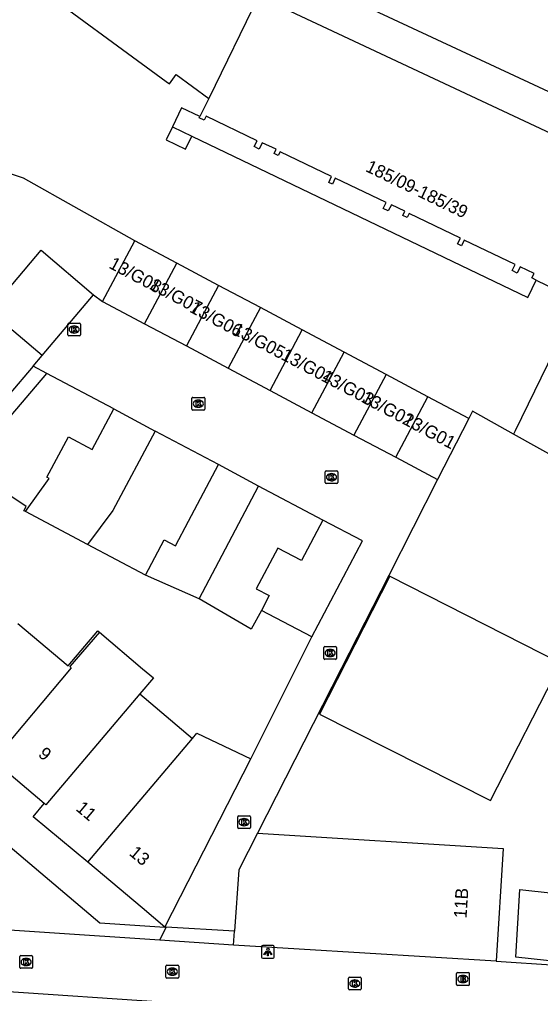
# Model space of a CAD drawing. Extents: x 160356 to 161355, y 381727 to 382845.
# Drawn here: x 160581.4 to 160622.2, y 382224.6 to 382300.8 of the extents above; entities that cross this region are included whole.
import ezdxf

# ---------------------------------------------------------------- set-up
doc = ezdxf.new("R2010")
doc.units = 0
for name, color, linetype in [('IMGEO_Brandkraan', 7, 'Continuous'), ('IMGEO_Kolk', 7, 'Continuous'), ('IMGEO_Lichtpunt', 7, 'Continuous'), ('IMGEO_Muur', 7, 'Continuous'), ('IMGEO_Pand', 7, 'Continuous'), ('IMGEO_Pand_nummerreeks', 7, 'Continuous'), ('IMGEO_Rijbaan_lokaal_open', 7, 'Continuous'), ('IMGEO_Voetpad_op_trap', 7, 'Continuous'), ('IMGEO_Voetpad_open', 7, 'Continuous')]:
    doc.layers.add(name, color=color, linetype=linetype)

msp = doc.modelspace()

# ---------------------------------------------------------------- linework, layer by layer
at = {"layer": 'IMGEO_Brandkraan'}
for p, q in [((160615.608, 382225.283), (160615.608, 382226.135)), ((160615.683, 382226.209), (160616.535, 382226.209)), ((160616.096, 382225.989), (160616.121, 382225.989)), ((160616.609, 382226.135), (160616.609, 382225.283)), ((160616.535, 382225.209), (160615.683, 382225.209)), ((160616.119, 382225.429), (160616.094, 382225.429))]:
    msp.add_line(p, q, dxfattribs=at)
for points in [[(160615.608, 382225.283), (160615.608, 382226.135)], [(160615.683, 382226.209), (160616.535, 382226.209)], [(160616.609, 382226.135), (160616.609, 382225.283)], [(160616.535, 382225.209), (160615.683, 382225.209)], [(160615.956, 382225.909), (160615.956, 382225.509), (160616.169, 382225.509)], [(160616.187, 382225.909), (160615.956, 382225.909)], [(160616.135, 382225.828), (160616.081, 382225.828), (160616.081, 382225.752)], [(160616.081, 382225.752), (160616.134, 382225.752)], [(160616.143, 382225.676), (160616.081, 382225.676), (160616.081, 382225.595)], [(160616.081, 382225.595), (160616.143, 382225.595)]]:
    msp.add_lwpolyline(points, dxfattribs=at)
for centre, radius, start, end in [((160615.685, 382226.133), 0.0765, 91.55205, 178.44795), ((160615.685, 382226.133), 0.0765, 91.55205, 178.44795), ((160616.533, 382226.133), 0.0765, 1.55205, 88.44795), ((160616.533, 382226.133), 0.0765, 1.55205, 88.44795), ((160615.685, 382225.285), 0.0765, 181.55205, 268.44795), ((160615.685, 382225.285), 0.0765, 181.55205, 268.44795), ((160616.136, 382225.79), 0.0379, 267.82845, 90.93552), ((160616.144, 382225.635), 0.0404, 269.87594, 90.50774), ((160616.175, 382225.76), 0.251, 268.66757, 293.53466), ((160616.191, 382225.764), 0.145, 59.4692, 91.53667), ((160616.216, 382225.811), 0.0922, 285.51372, 58.15012), ((160616.221, 382225.619), 0.105, 301.31148, 78.98903), ((160616.533, 382225.285), 0.0765, 271.55205, 358.44795), ((160616.533, 382225.285), 0.0765, 271.55205, 358.44795)]:
    msp.add_arc(centre, radius, start, end, dxfattribs=at)
for centre, major_axis, ratio, start_param, end_param in [((160616.095, 382225.709), (-0.387, 0.002), 0.722429, 4.712389, 7.853982), ((160616.12, 382225.709), (-0.39, 0.002), 0.717154, 1.570796, 4.712389)]:
    msp.add_ellipse(centre, major_axis=major_axis, ratio=ratio, start_param=start_param, end_param=end_param, dxfattribs=at)
at = {"layer": 'IMGEO_Kolk'}
for p, q in [((160585.247, 382277.054), (160586.099, 382277.054)), ((160585.172, 382276.128), (160585.172, 382276.98)), ((160585.683, 382276.274), (160585.658, 382276.274)), ((160585.66, 382276.834), (160585.685, 382276.834)), ((160586.173, 382276.98), (160586.173, 382276.128)), ((160586.099, 382276.054), (160585.247, 382276.054)), ((160594.892, 382270.312), (160594.892, 382271.164)), ((160594.967, 382271.238), (160595.819, 382271.238)), ((160595.38, 382271.018), (160595.405, 382271.018)), ((160595.893, 382271.164), (160595.893, 382270.312)), ((160595.819, 382270.238), (160594.967, 382270.238)), ((160595.403, 382270.458), (160595.378, 382270.458)), ((160605.318, 382264.562), (160605.318, 382265.414)), ((160605.393, 382265.488), (160606.245, 382265.488)), ((160605.806, 382265.268), (160605.831, 382265.268)), ((160606.319, 382265.414), (160606.319, 382264.562)), ((160606.245, 382264.488), (160605.393, 382264.488)), ((160605.829, 382264.708), (160605.804, 382264.708)), ((160605.211, 382250.806), (160605.211, 382251.658)), ((160605.286, 382251.732), (160606.138, 382251.732)), ((160605.699, 382251.512), (160605.724, 382251.512)), ((160606.212, 382251.658), (160606.212, 382250.806)), ((160606.138, 382250.732), (160605.286, 382250.732)), ((160605.722, 382250.952), (160605.697, 382250.952)), ((160598.475, 382237.562), (160598.475, 382238.414)), ((160598.55, 382238.488), (160599.402, 382238.488)), ((160598.963, 382238.268), (160598.988, 382238.268)), ((160599.476, 382238.414), (160599.476, 382237.562)), ((160599.402, 382237.488), (160598.55, 382237.488)), ((160598.986, 382237.708), (160598.961, 382237.708)), ((160581.411, 382226.62), (160581.411, 382227.472)), ((160581.486, 382227.546), (160582.338, 382227.546)), ((160582.412, 382227.472), (160582.412, 382226.62)), ((160581.922, 382226.766), (160581.897, 382226.766)), ((160581.899, 382227.326), (160581.924, 382227.326)), ((160592.857, 382225.86), (160592.857, 382226.712)), ((160592.932, 382226.786), (160593.784, 382226.786)), ((160593.858, 382226.712), (160593.858, 382225.86)), ((160582.338, 382226.546), (160581.486, 382226.546)), ((160593.368, 382226.006), (160593.343, 382226.006)), ((160593.345, 382226.566), (160593.37, 382226.566)), ((160593.784, 382225.786), (160592.932, 382225.786)), ((160607.141, 382224.926), (160607.141, 382225.778)), ((160607.216, 382225.852), (160608.068, 382225.852)), ((160607.629, 382225.632), (160607.654, 382225.632)), ((160608.142, 382225.778), (160608.142, 382224.926)), ((160608.068, 382224.852), (160607.216, 382224.852)), ((160607.652, 382225.072), (160607.627, 382225.072))]:
    msp.add_line(p, q, dxfattribs=at)
for points in [[(160585.247, 382277.054), (160586.099, 382277.054)], [(160585.172, 382276.128), (160585.172, 382276.98)], [(160585.493, 382276.754), (160585.616, 382276.754), (160585.616, 382276.603), (160585.746, 382276.754), (160585.91, 382276.754), (160585.764, 382276.603), (160585.917, 382276.354), (160585.765, 382276.354), (160585.68, 382276.518), (160585.616, 382276.451), (160585.616, 382276.354), (160585.493, 382276.354), (160585.493, 382276.754)], [(160586.173, 382276.98), (160586.173, 382276.128)], [(160586.099, 382276.054), (160585.247, 382276.054)], [(160594.892, 382270.312), (160594.892, 382271.164)], [(160594.967, 382271.238), (160595.819, 382271.238)], [(160595.213, 382270.938), (160595.336, 382270.938), (160595.336, 382270.787), (160595.466, 382270.938), (160595.63, 382270.938), (160595.484, 382270.787), (160595.637, 382270.538), (160595.485, 382270.538), (160595.4, 382270.702), (160595.336, 382270.635), (160595.336, 382270.538), (160595.213, 382270.538), (160595.213, 382270.938)], [(160595.893, 382271.164), (160595.893, 382270.312)], [(160595.819, 382270.238), (160594.967, 382270.238)], [(160605.318, 382264.562), (160605.318, 382265.414)], [(160605.393, 382265.488), (160606.245, 382265.488)], [(160605.639, 382265.188), (160605.762, 382265.188), (160605.762, 382265.037), (160605.892, 382265.188), (160606.056, 382265.188), (160605.91, 382265.037), (160606.063, 382264.788), (160605.911, 382264.788), (160605.826, 382264.952), (160605.762, 382264.885), (160605.762, 382264.788), (160605.639, 382264.788), (160605.639, 382265.188)], [(160606.319, 382265.414), (160606.319, 382264.562)], [(160606.245, 382264.488), (160605.393, 382264.488)], [(160605.211, 382250.806), (160605.211, 382251.658)], [(160605.286, 382251.732), (160606.138, 382251.732)], [(160605.532, 382251.432), (160605.655, 382251.432), (160605.655, 382251.281), (160605.785, 382251.432), (160605.949, 382251.432), (160605.803, 382251.281), (160605.956, 382251.032), (160605.804, 382251.032), (160605.719, 382251.196), (160605.655, 382251.129), (160605.655, 382251.032), (160605.532, 382251.032), (160605.532, 382251.432)], [(160606.212, 382251.658), (160606.212, 382250.806)], [(160606.138, 382250.732), (160605.286, 382250.732)], [(160598.475, 382237.562), (160598.475, 382238.414)], [(160598.55, 382238.488), (160599.402, 382238.488)], [(160598.796, 382238.188), (160598.919, 382238.188), (160598.919, 382238.037), (160599.049, 382238.188), (160599.213, 382238.188), (160599.067, 382238.037), (160599.22, 382237.788), (160599.068, 382237.788), (160598.983, 382237.952), (160598.919, 382237.885), (160598.919, 382237.788), (160598.796, 382237.788), (160598.796, 382238.188)], [(160599.476, 382238.414), (160599.476, 382237.562)], [(160599.402, 382237.488), (160598.55, 382237.488)], [(160581.411, 382226.62), (160581.411, 382227.472)], [(160581.486, 382227.546), (160582.338, 382227.546)], [(160582.412, 382227.472), (160582.412, 382226.62)], [(160581.732, 382227.246), (160581.855, 382227.246), (160581.855, 382227.095), (160581.985, 382227.246), (160582.149, 382227.246), (160582.003, 382227.095), (160582.156, 382226.846), (160582.004, 382226.846), (160581.919, 382227.01), (160581.855, 382226.943), (160581.855, 382226.846), (160581.732, 382226.846), (160581.732, 382227.246)], [(160592.857, 382225.86), (160592.857, 382226.712)], [(160592.932, 382226.786), (160593.784, 382226.786)], [(160593.858, 382226.712), (160593.858, 382225.86)], [(160582.338, 382226.546), (160581.486, 382226.546)], [(160593.178, 382226.486), (160593.301, 382226.486), (160593.301, 382226.335), (160593.431, 382226.486), (160593.595, 382226.486), (160593.449, 382226.335), (160593.602, 382226.086), (160593.45, 382226.086), (160593.365, 382226.25), (160593.301, 382226.183), (160593.301, 382226.086), (160593.178, 382226.086), (160593.178, 382226.486)], [(160593.784, 382225.786), (160592.932, 382225.786)], [(160607.141, 382224.926), (160607.141, 382225.778)], [(160607.216, 382225.852), (160608.068, 382225.852)], [(160607.462, 382225.552), (160607.585, 382225.552), (160607.585, 382225.401), (160607.715, 382225.552), (160607.879, 382225.552), (160607.733, 382225.401), (160607.886, 382225.152), (160607.734, 382225.152), (160607.649, 382225.316), (160607.585, 382225.249), (160607.585, 382225.152), (160607.462, 382225.152), (160607.462, 382225.552)], [(160608.142, 382225.778), (160608.142, 382224.926)], [(160608.068, 382224.852), (160607.216, 382224.852)]]:
    msp.add_lwpolyline(points, dxfattribs=at)
for centre, start, end in [((160585.249, 382276.978), 91.55205, 178.44795), ((160585.249, 382276.978), 91.55205, 178.44795), ((160586.097, 382276.978), 1.55205, 88.44795), ((160586.097, 382276.978), 1.55205, 88.44795), ((160585.249, 382276.13), 181.55205, 268.44795), ((160585.249, 382276.13), 181.55205, 268.44795), ((160586.097, 382276.13), 271.55205, 358.44795), ((160586.097, 382276.13), 271.55205, 358.44795), ((160594.969, 382271.162), 91.55205, 178.44795), ((160594.969, 382271.162), 91.55205, 178.44795), ((160595.817, 382271.162), 1.55205, 88.44795), ((160595.817, 382271.162), 1.55205, 88.44795), ((160594.969, 382270.314), 181.55205, 268.44795), ((160594.969, 382270.314), 181.55205, 268.44795), ((160595.817, 382270.314), 271.55205, 358.44795), ((160595.817, 382270.314), 271.55205, 358.44795), ((160605.395, 382265.412), 91.55205, 178.44795), ((160605.395, 382265.412), 91.55205, 178.44795), ((160606.243, 382265.412), 1.55205, 88.44795), ((160606.243, 382265.412), 1.55205, 88.44795), ((160605.395, 382264.564), 181.55205, 268.44795), ((160605.395, 382264.564), 181.55205, 268.44795), ((160606.243, 382264.564), 271.55205, 358.44795), ((160606.243, 382264.564), 271.55205, 358.44795), ((160605.288, 382251.656), 91.55205, 178.44795), ((160605.288, 382251.656), 91.55205, 178.44795), ((160606.136, 382251.656), 1.55205, 88.44795), ((160606.136, 382251.656), 1.55205, 88.44795), ((160605.288, 382250.808), 181.55205, 268.44795), ((160605.288, 382250.808), 181.55205, 268.44795), ((160606.136, 382250.808), 271.55205, 358.44795), ((160606.136, 382250.808), 271.55205, 358.44795), ((160598.552, 382238.412), 91.55205, 178.44795), ((160598.552, 382238.412), 91.55205, 178.44795), ((160599.4, 382238.412), 1.55205, 88.44795), ((160599.4, 382238.412), 1.55205, 88.44795), ((160598.552, 382237.564), 181.55205, 268.44795), ((160598.552, 382237.564), 181.55205, 268.44795), ((160599.4, 382237.564), 271.55205, 358.44795), ((160599.4, 382237.564), 271.55205, 358.44795), ((160581.488, 382227.47), 91.55205, 178.44795), ((160581.488, 382227.47), 91.55205, 178.44795), ((160582.336, 382227.47), 1.55205, 88.44795), ((160582.336, 382227.47), 1.55205, 88.44795), ((160592.934, 382226.71), 91.55205, 178.44795), ((160592.934, 382226.71), 91.55205, 178.44795), ((160593.782, 382226.71), 1.55205, 88.44795), ((160593.782, 382226.71), 1.55205, 88.44795), ((160581.488, 382226.622), 181.55205, 268.44795), ((160581.488, 382226.622), 181.55205, 268.44795), ((160582.336, 382226.622), 271.55205, 358.44795), ((160582.336, 382226.622), 271.55205, 358.44795), ((160592.934, 382225.862), 181.55205, 268.44795), ((160592.934, 382225.862), 181.55205, 268.44795), ((160593.782, 382225.862), 271.55205, 358.44795), ((160593.782, 382225.862), 271.55205, 358.44795), ((160607.218, 382225.776), 91.55205, 178.44795), ((160607.218, 382225.776), 91.55205, 178.44795), ((160608.066, 382225.776), 1.55205, 88.44795), ((160608.066, 382225.776), 1.55205, 88.44795), ((160607.218, 382224.928), 181.55205, 268.44795), ((160607.218, 382224.928), 181.55205, 268.44795), ((160608.066, 382224.928), 271.55205, 358.44795), ((160608.066, 382224.928), 271.55205, 358.44795)]:
    msp.add_arc(centre, 0.0765, start, end, dxfattribs=at)
for centre, major_axis, ratio, start_param, end_param in [((160585.659, 382276.554), (-0.387, 0.002), 0.722429, 4.712389, 7.853982), ((160585.684, 382276.554), (-0.39, 0.002), 0.717154, 1.570796, 4.712389), ((160595.379, 382270.738), (-0.387, 0.002), 0.722429, 4.712389, 7.853982), ((160595.404, 382270.738), (-0.39, 0.002), 0.717154, 1.570796, 4.712389), ((160605.805, 382264.988), (-0.387, 0.002), 0.722429, 4.712389, 7.853982), ((160605.83, 382264.988), (-0.39, 0.002), 0.717154, 1.570796, 4.712389), ((160605.698, 382251.232), (-0.387, 0.002), 0.722429, 4.712389, 7.853982), ((160605.723, 382251.232), (-0.39, 0.002), 0.717154, 1.570796, 4.712389), ((160598.962, 382237.988), (-0.387, 0.002), 0.722429, 4.712389, 7.853982), ((160598.987, 382237.988), (-0.39, 0.002), 0.717154, 1.570796, 4.712389), ((160581.898, 382227.046), (-0.387, 0.002), 0.722429, 4.712389, 7.853982), ((160581.923, 382227.046), (-0.39, 0.002), 0.717154, 1.570796, 4.712389), ((160593.344, 382226.286), (-0.387, 0.002), 0.722429, 4.712389, 7.853982), ((160593.369, 382226.286), (-0.39, 0.002), 0.717154, 1.570796, 4.712389), ((160607.628, 382225.352), (-0.387, 0.002), 0.722429, 4.712389, 7.853982), ((160607.653, 382225.352), (-0.39, 0.002), 0.717154, 1.570796, 4.712389)]:
    msp.add_ellipse(centre, major_axis=major_axis, ratio=ratio, start_param=start_param, end_param=end_param, dxfattribs=at)
at = {"layer": 'IMGEO_Lichtpunt'}
for p, q in [((160600.345, 382228.233), (160600.345, 382227.426)), ((160600.345, 382228.233), (160600.345, 382227.426)), ((160601.247, 382228.328), (160600.439, 382228.328)), ((160601.247, 382228.328), (160600.439, 382228.328)), ((160601.341, 382227.426), (160601.341, 382228.233)), ((160601.341, 382227.426), (160601.341, 382228.233)), ((160600.439, 382227.332), (160601.247, 382227.332)), ((160600.439, 382227.332), (160601.247, 382227.332))]:
    msp.add_line(p, q, dxfattribs=at)
for points in [[(160600.719, 382227.897), (160600.758, 382227.869), (160600.57, 382227.607), (160600.532, 382227.634), (160600.719, 382227.897)], [(160600.821, 382227.849), (160600.868, 382227.849), (160600.868, 382227.527), (160600.821, 382227.527), (160600.821, 382227.849)], [(160600.931, 382227.869), (160600.969, 382227.896), (160601.156, 382227.634), (160601.117, 382227.606), (160600.931, 382227.869)]]:
    msp.add_lwpolyline(points, dxfattribs=at)
msp.add_circle((160600.844, 382228.031), 0.0994, dxfattribs=at)
for centre, start, end in [((160600.439, 382228.233), 90, 180), ((160600.439, 382228.233), 90, 180), ((160601.247, 382228.233), 0, 90), ((160601.247, 382228.233), 0, 90), ((160600.439, 382227.426), 180, 270), ((160600.439, 382227.426), 180, 270), ((160601.247, 382227.426), 270, 0), ((160601.247, 382227.426), 270, 360)]:
    msp.add_arc(centre, 0.0946, start, end, dxfattribs=at)
at = {"layer": 'IMGEO_Muur'}
msp.add_lwpolyline([(160618.701, 382227.096), (160628.15, 382226.469), (160633.664, 382237.246)], dxfattribs=at)
at = {"layer": 'IMGEO_Pand'}
for points in [[(160602.684, 382304.568), (160625.056, 382294.138)], [(160581.837, 382304.092), (160592.884, 382295.963), (160593.126, 382295.785), (160593.659, 382296.51), (160596.203, 382294.64)], [(160600.114, 382302.653), (160596.203, 382294.64)], [(160628.955, 382264.141), (160632.865, 382272.306), (160632.67, 382272.4), (160637.325, 382282.078), (160635.529, 382282.942), (160636.742, 382285.453), (160600.114, 382302.653)], [(160596.203, 382294.64), (160595.507, 382293.214)], [(160621.852, 382280.417), (160621.509, 382280.583), (160621.68, 382280.944), (160620.592, 382281.465), (160620.354, 382280.969), (160619.962, 382281.157), (160620.195, 382281.644), (160616.209, 382283.552), (160615.993, 382283.101), (160615.696, 382283.244), (160615.912, 382283.695), (160611.891, 382285.62), (160611.746, 382285.318), (160611.408, 382285.48), (160611.563, 382285.804), (160610.504, 382286.312), (160610.261, 382285.829), (160609.874, 382286.024), (160610.108, 382286.489), (160606.113, 382288.392), (160605.885, 382287.926), (160605.598, 382288.068), (160605.828, 382288.524), (160601.801, 382290.464), (160601.654, 382290.168), (160601.323, 382290.333), (160601.483, 382290.655), (160600.39, 382291.159), (160600.156, 382290.678), (160599.775, 382290.863), (160599.998, 382291.332), (160595.998, 382293.241), (160595.854, 382292.945), (160595.467, 382293.133), (160595.507, 382293.214)], [(160587.9, 382278.745), (160590.422, 382283.49)], [(160593.7, 382281.747), (160590.422, 382283.49)], [(160583.171, 382274.504), (160579.051, 382277.995), (160583.078, 382282.749), (160587.198, 382279.258)], [(160591.178, 382277.002), (160593.7, 382281.747)], [(160596.978, 382280.004), (160593.7, 382281.747)], [(160621.852, 382280.417), (160625.79, 382278.518), (160625.708, 382278.346), (160625.996, 382278.208), (160626.078, 382278.379), (160627.14, 382277.869)], [(160596.978, 382280.004), (160594.456, 382275.26)], [(160600.256, 382278.262), (160596.978, 382280.004)], [(160583.171, 382274.504), (160587.198, 382279.258)], [(160587.9, 382278.745), (160591.178, 382277.002)], [(160600.256, 382278.262), (160597.734, 382273.517)], [(160603.534, 382276.519), (160600.256, 382278.262)], [(160591.178, 382277.002), (160594.456, 382275.26)], [(160601.012, 382271.774), (160603.534, 382276.519)], [(160606.812, 382274.777), (160603.534, 382276.519)], [(160594.456, 382275.26), (160597.734, 382273.517)], [(160604.289, 382270.032), (160606.812, 382274.777)], [(160610.09, 382273.034), (160606.812, 382274.777)], [(160626.298, 382273.351), (160623.212, 382274.839), (160620.207, 382268.622), (160620.078, 382268.352)], [(160597.734, 382273.517), (160601.012, 382271.774)], [(160577.31, 382265.756), (160580.302, 382269.289), (160583.532, 382273.105)], [(160588.766, 382270.329), (160583.532, 382273.105)], [(160610.09, 382273.034), (160607.567, 382268.289)], [(160613.368, 382271.291), (160610.09, 382273.034)], [(160601.012, 382271.774), (160604.289, 382270.032)], [(160610.845, 382266.547), (160613.368, 382271.291)], [(160616.565, 382269.591), (160613.368, 382271.291)], [(160581.861, 382262.295), (160583.721, 382264.877), (160583.527, 382264.981), (160585.219, 382268.147), (160587.071, 382267.157), (160588.766, 382270.329)], [(160588.766, 382270.329), (160592.025, 382268.6)], [(160620.078, 382268.352), (160616.85, 382270.149), (160616.565, 382269.591)], [(160604.289, 382270.032), (160607.567, 382268.289)], [(160616.565, 382269.591), (160614.123, 382264.804)], [(160592.025, 382268.6), (160588.7, 382262.375), (160586.706, 382259.726)], [(160596.979, 382265.972), (160592.025, 382268.6)], [(160607.567, 382268.289), (160610.845, 382266.547)], [(160628.666, 382263.571), (160628.475, 382263.678), (160628.076, 382263.899), (160620.078, 382268.352)], [(160610.845, 382266.547), (160614.123, 382264.804)], [(160581.861, 382262.295), (160581.741, 382262.358), (160581.916, 382262.695), (160577.31, 382265.756)], [(160591.247, 382257.318), (160592.718, 382260.093), (160593.61, 382259.62), (160594.636, 382261.555), (160596.979, 382265.972)], [(160600.114, 382264.287), (160596.979, 382265.972)], [(160614.123, 382264.804), (160610.3, 382257.288)], [(160595.47, 382255.465), (160600.114, 382264.287)], [(160605.141, 382261.637), (160600.114, 382264.287)], [(160586.706, 382259.726), (160581.861, 382262.295)], [(160605.141, 382261.637), (160603.467, 382258.462), (160601.609, 382259.441), (160599.93, 382256.256), (160600.93, 382255.729), (160600.326, 382254.567)], [(160604.28, 382252.482), (160608.244, 382260.001), (160605.141, 382261.637)], [(160591.247, 382257.318), (160586.706, 382259.726)], [(160595.47, 382255.465), (160591.247, 382257.318)], [(160610.389, 382257.243), (160604.886, 382246.452), (160618.279, 382239.673), (160623.772, 382250.439)], [(160610.3, 382257.288), (160610.389, 382257.243)], [(160610.389, 382257.243), (160623.772, 382250.439)], [(160600.326, 382254.567), (160599.542, 382253.081), (160595.47, 382255.465)], [(160604.28, 382252.482), (160600.326, 382254.567)], [(160581.267, 382253.545), (160585.2, 382250.219), (160587.532, 382252.969), (160587.651, 382252.868)], [(160587.651, 382252.868), (160585.33, 382250.166), (160585.444, 382250.068), (160579.333, 382242.82)], [(160587.651, 382252.868), (160591.034, 382250), (160591.88, 382249.283), (160590.813, 382248.024)], [(160590.813, 382248.024), (160583.445, 382239.342), (160583.331, 382239.439)], [(160590.813, 382248.024), (160594.925, 382244.539)], [(160586.731, 382234.841), (160594.925, 382244.539)], [(160594.925, 382244.539), (160595.28, 382244.96), (160599.507, 382242.933)], [(160583.331, 382239.439), (160579.333, 382242.82)], [(160592.762, 382229.766), (160599.507, 382242.933)], [(160586.731, 382234.841), (160582.47, 382238.415), (160583.331, 382239.439)], [(160600.025, 382237.133), (160598.557, 382234.251), (160598.228, 382229.453)], [(160600.025, 382237.133), (160619.255, 382235.929), (160618.701, 382227.096)], [(160592.762, 382229.766), (160590.985, 382231.273), (160586.731, 382234.841)], [(160628.19, 382226.548), (160620.242, 382227.418), (160620.574, 382232.705), (160630.77, 382231.589)], [(160598.152, 382228.345), (160598.228, 382229.453)], [(160618.701, 382227.096), (160598.152, 382228.345)]]:
    msp.add_lwpolyline(points, dxfattribs=at)
at = {"layer": 'IMGEO_Rijbaan_lokaal_open'}
for points in [[(160595.507, 382293.214), (160594.068, 382293.904), (160593.359, 382292.425)], [(160593.359, 382292.425), (160592.866, 382291.397), (160594.395, 382290.664), (160594.887, 382291.692)], [(160594.887, 382291.692), (160621.195, 382279.049), (160621.221, 382279.105), (160621.852, 382280.417)], [(160590.422, 382283.49), (160581.704, 382288.41), (160579.335, 382289.191)], [(160587.198, 382279.258), (160587.9, 382278.745)], [(160582.465, 382273.671), (160583.171, 382274.504)], [(160583.532, 382273.105), (160582.465, 382273.671)], [(160610.3, 382257.288), (160606.582, 382250), (160600.025, 382237.133)], [(160599.507, 382242.933), (160604.28, 382252.482)], [(160592.388, 382228.741), (160574.693, 382229.924), (160574.104, 382229.963)], [(160592.388, 382228.741), (160592.875, 382229.775)], [(160592.875, 382229.775), (160592.762, 382229.766)], [(160598.228, 382229.453), (160592.875, 382229.775)], [(160598.152, 382228.345), (160592.388, 382228.741)], [(160618.701, 382227.096), (160628.15, 382226.469), (160628.19, 382226.548)], [(160574.354, 382225.146), (160598.291, 382223.527), (160598.324, 382223.525)]]:
    msp.add_lwpolyline(points, dxfattribs=at)
at = {"layer": 'IMGEO_Voetpad_op_trap'}
msp.add_lwpolyline([(160593.359, 382292.425), (160594.887, 382291.692)], dxfattribs=at)
at = {"layer": 'IMGEO_Voetpad_open'}
for points in [[(160582.465, 382273.671), (160580.571, 382271.436)], [(160564.068, 382250.099), (160564.185, 382250), (160587.69, 382230.118), (160592.762, 382229.766)]]:
    msp.add_lwpolyline(points, dxfattribs=at)

# ---------------------------------------------------------------- texts
at = {"layer": 'IMGEO_Pand_nummerreeks'}
for s, rotation, p in [('185/09-185/39', 334.22263, (160608.415, 382288.971)), ('13/G08', 332.05067, (160588.317, 382281.407)), ('13/G07', 332.05067, (160591.48, 382279.769)), ('13/G06', 332.05067, (160594.645, 382277.961)), ('13/G05', 332.05067, (160597.98, 382276.265)), ('13/G04', 332.05067, (160601.792, 382274.262)), ('13/G03', 332.05067, (160604.935, 382272.595)), ('13/G02', 332.05067, (160608.072, 382270.93)), ('13/G01', 332.05067, (160611.318, 382269.208)), ('9', 319.77974, (160582.786, 382243.199)), ('11', 320.01158, (160585.742, 382238.959)), ('13', 320.01158, (160589.913, 382235.462)), ('11B', 86.41115, (160616.387, 382230.436))]:
    msp.add_text(s, height=1, rotation=rotation, dxfattribs=at).set_placement(p)

doc.saveas('drawing.dxf')
